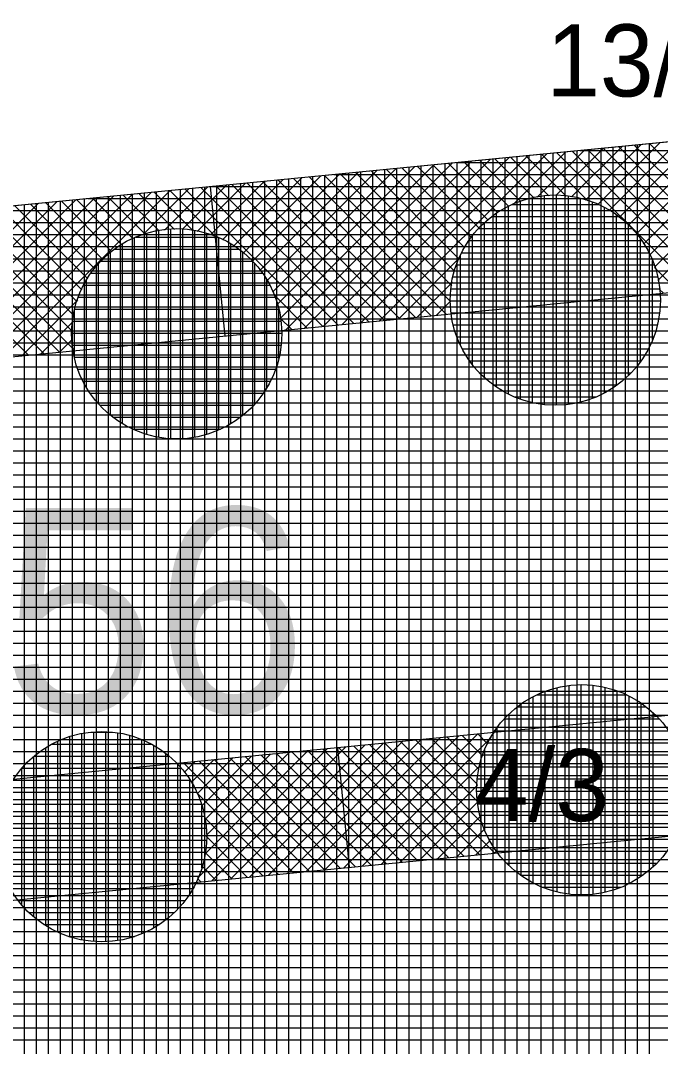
# Model space of a CAD drawing. Extents: x -566461 to -565198, y -1096301 to -1095707.
# Drawn here: x -566328.95 to -566318.3, y -1095853.58 to -1095836.51 of the extents above; entities that cross this region are included whole.
import ezdxf

# ---------------------------------------------------------------- set-up
doc = ezdxf.new("R2010")
doc.units = 0
for name, color, linetype in [('Vrstva 1', 7, 'Continuous'), ('Vrstva 18', 7, 'Continuous'), ('Vrstva 40', 7, 'Continuous'), ('Vrstva 41', 7, 'Continuous'), ('Vrstva 42', 7, 'Continuous'), ('Vrstva 43', 7, 'Continuous'), ('Vrstva 44', 7, 'Continuous')]:
    doc.layers.add(name, color=color, linetype=linetype)

msp = doc.modelspace()

# ---------------------------------------------------------------- linework, layer by layer
at = {"layer": 'Vrstva 1'}
msp.add_line((-566305.22, -1095837.26), (-566355.65, -1095842.19), dxfattribs=at)
at = {"layer": 'Vrstva 41'}
for p, q in [((-566315.801, -1095838.294), (-566318.342, -1095840.835)), ((-566317.369, -1095838.448), (-566318.837, -1095839.916)), ((-566317.055, -1095838.417), (-566318.702, -1095840.064)), ((-566316.742, -1095838.386), (-566318.583, -1095840.228)), ((-566316.428, -1095838.356), (-566318.482, -1095840.409)), ((-566316.115, -1095838.325), (-566318.4, -1095840.61)), ((-566319.25, -1095838.632), (-566320.039, -1095839.421)), ((-566318.936, -1095838.601), (-566319.779, -1095839.443)), ((-566318.623, -1095838.57), (-566319.548, -1095839.495)), ((-566318.309, -1095838.54), (-566319.341, -1095839.571)), ((-566319.251, -1095838.632), (-566316.963, -1095840.92)), ((-566317.996, -1095838.509), (-566319.156, -1095839.669)), ((-566318.994, -1095838.607), (-566316.706, -1095840.894)), ((-566317.682, -1095838.478), (-566318.988, -1095839.784)), ((-566318.736, -1095838.581), (-566316.448, -1095840.869)), ((-566318.478, -1095838.556), (-566316.19, -1095840.844)), ((-566321.131, -1095838.815), (-566323.915, -1095841.599)), ((-566320.817, -1095838.785), (-566323.601, -1095841.569)), ((-566320.504, -1095838.754), (-566323.288, -1095841.538)), ((-566320.19, -1095838.723), (-566322.974, -1095841.507)), ((-566321.055, -1095838.808), (-566320.406, -1095839.457)), ((-566320.797, -1095838.783), (-566320.155, -1095839.425)), ((-566319.877, -1095838.693), (-566320.752, -1095839.568)), ((-566320.54, -1095838.758), (-566319.868, -1095839.429)), ((-566319.563, -1095838.662), (-566320.349, -1095839.448)), ((-566320.282, -1095838.732), (-566319.508, -1095839.507)), ((-566320.024, -1095838.707), (-566317.736, -1095840.995)), ((-566319.767, -1095838.682), (-566317.479, -1095840.97)), ((-566319.509, -1095838.657), (-566317.221, -1095840.945)), ((-566322.698, -1095838.969), (-566324.755, -1095841.025)), ((-566322.385, -1095838.938), (-566324.681, -1095841.234)), ((-566322.071, -1095838.907), (-566324.631, -1095841.467)), ((-566321.758, -1095838.877), (-566324.542, -1095841.66)), ((-566321.444, -1095838.846), (-566324.228, -1095841.63)), ((-566322.859, -1095838.984), (-566321.555, -1095840.288)), ((-566322.601, -1095838.959), (-566321.442, -1095840.118)), ((-566322.343, -1095838.934), (-566321.312, -1095839.965)), ((-566322.086, -1095838.909), (-566321.166, -1095839.828)), ((-566321.828, -1095838.884), (-566321.004, -1095839.707)), ((-566321.57, -1095838.858), (-566320.825, -1095839.604)), ((-566321.313, -1095838.833), (-566320.626, -1095839.52)), ((-566324.579, -1095839.153), (-566325.586, -1095840.159)), ((-566324.266, -1095839.122), (-566325.405, -1095840.261)), ((-566323.952, -1095839.091), (-566325.242, -1095840.381)), ((-566323.639, -1095839.061), (-566325.096, -1095840.517)), ((-566323.325, -1095839.03), (-566324.965, -1095840.669)), ((-566323.012, -1095838.999), (-566324.851, -1095840.838)), ((-566324.662, -1095839.161), (-566322.374, -1095841.449)), ((-566324.404, -1095839.135), (-566322.117, -1095841.423)), ((-566324.147, -1095839.11), (-566321.859, -1095841.398)), ((-566323.889, -1095839.085), (-566321.789, -1095841.186)), ((-566323.632, -1095839.06), (-566321.772, -1095840.92)), ((-566323.374, -1095839.035), (-566321.722, -1095840.686)), ((-566323.116, -1095839.01), (-566321.649, -1095840.476)), ((-566326.147, -1095839.306), (-566326.917, -1095840.076)), ((-566325.833, -1095839.275), (-566326.551, -1095839.993)), ((-566325.52, -1095839.244), (-566326.26, -1095839.985)), ((-566326.208, -1095839.312), (-566323.92, -1095841.6)), ((-566325.206, -1095839.214), (-566326.007, -1095840.015)), ((-566325.95, -1095839.287), (-566323.662, -1095841.575)), ((-566324.893, -1095839.183), (-566325.785, -1095840.075)), ((-566325.693, -1095839.261), (-566323.405, -1095841.549)), ((-566325.435, -1095839.236), (-566323.147, -1095841.524)), ((-566325.177, -1095839.211), (-566322.89, -1095841.499)), ((-566324.92, -1095839.186), (-566322.632, -1095841.474)), ((-566328.028, -1095839.49), (-566330.811, -1095842.273)), ((-566327.714, -1095839.459), (-566330.498, -1095842.243)), ((-566327.401, -1095839.428), (-566330.184, -1095842.212)), ((-566327.087, -1095839.398), (-566329.871, -1095842.181)), ((-566326.774, -1095839.367), (-566329.557, -1095842.151)), ((-566326.46, -1095839.336), (-566329.244, -1095842.12)), ((-566328.012, -1095839.488), (-566327.261, -1095840.239)), ((-566327.754, -1095839.463), (-566327.077, -1095840.14)), ((-566327.496, -1095839.438), (-566326.873, -1095840.061)), ((-566327.239, -1095839.413), (-566326.644, -1095840.007)), ((-566326.981, -1095839.387), (-566326.386, -1095839.982)), ((-566326.723, -1095839.362), (-566326.082, -1095840.003)), ((-566326.466, -1095839.337), (-566325.692, -1095840.111)), ((-566328.655, -1095839.551), (-566331.194, -1095842.091)), ((-566328.341, -1095839.52), (-566331.125, -1095842.304)), ((-566329.815, -1095839.664), (-566328.061, -1095841.418)), ((-566329.558, -1095839.639), (-566328.007, -1095841.19)), ((-566329.3, -1095839.614), (-566327.927, -1095840.987)), ((-566329.042, -1095839.589), (-566327.827, -1095840.804)), ((-566328.785, -1095839.564), (-566327.71, -1095840.638)), ((-566328.527, -1095839.538), (-566327.576, -1095840.489)), ((-566328.269, -1095839.513), (-566327.427, -1095840.356)), ((-566331.104, -1095839.79), (-566328.816, -1095842.078)), ((-566330.846, -1095839.765), (-566328.558, -1095842.053)), ((-566330.588, -1095839.74), (-566328.3, -1095842.028)), ((-566330.331, -1095839.715), (-566328.068, -1095841.977)), ((-566330.073, -1095839.69), (-566328.088, -1095841.675)), ((-566321.642, -1095840.458), (-566322.661, -1095841.477)), ((-566318.397, -1095840.618), (-566317.994, -1095841.02)), ((-566321.762, -1095840.861), (-566322.347, -1095841.446)), ((-566318.319, -1095840.978), (-566318.252, -1095841.046)), ((-566327.994, -1095841.153), (-566328.93, -1095842.089)), ((-566324.741, -1095841.062), (-566324.178, -1095841.625)), ((-566321.789, -1095841.171), (-566322.034, -1095841.415)), ((-566328.077, -1095841.519), (-566328.617, -1095842.059)), ((-566324.633, -1095841.452), (-566324.435, -1095841.65)), ((-566328.085, -1095841.81), (-566328.303, -1095842.028)), ((-566321.341, -1095848.381), (-566323.569, -1095850.609)), ((-566321.339, -1095848.381), (-566321.172, -1095848.548)), ((-566321.082, -1095848.356), (-566321.07, -1095848.368)), ((-566322.909, -1095848.534), (-566325.136, -1095850.762)), ((-566322.595, -1095848.504), (-566324.823, -1095850.732)), ((-566322.282, -1095848.473), (-566324.509, -1095850.701)), ((-566321.968, -1095848.443), (-566324.196, -1095850.67)), ((-566321.655, -1095848.412), (-566323.883, -1095850.64)), ((-566321.117, -1095848.44), (-566323.256, -1095850.578)), ((-566322.885, -1095848.532), (-566321.054, -1095850.363)), ((-566322.628, -1095848.507), (-566321.252, -1095849.883)), ((-566322.37, -1095848.482), (-566321.336, -1095849.515)), ((-566322.112, -1095848.457), (-566321.345, -1095849.224)), ((-566321.855, -1095848.431), (-566321.316, -1095848.971)), ((-566321.597, -1095848.406), (-566321.256, -1095848.748)), ((-566323.849, -1095848.626), (-566326.002, -1095850.779)), ((-566324.163, -1095848.657), (-566325.89, -1095850.384)), ((-566324.79, -1095848.718), (-566325.883, -1095849.812)), ((-566324.476, -1095848.688), (-566325.86, -1095850.072)), ((-566323.536, -1095848.596), (-566325.763, -1095850.824)), ((-566323.222, -1095848.565), (-566325.45, -1095850.793)), ((-566324.689, -1095848.708), (-566322.858, -1095850.54)), ((-566324.431, -1095848.683), (-566322.6, -1095850.514)), ((-566324.174, -1095848.658), (-566322.343, -1095850.489)), ((-566323.916, -1095848.633), (-566322.085, -1095850.464)), ((-566323.658, -1095848.608), (-566321.827, -1095850.439)), ((-566323.401, -1095848.583), (-566321.57, -1095850.414)), ((-566323.143, -1095848.557), (-566321.312, -1095850.388)), ((-566326.357, -1095848.872), (-566326.358, -1095848.873)), ((-566326.235, -1095848.86), (-566324.404, -1095850.691)), ((-566326.043, -1095848.841), (-566326.226, -1095849.023)), ((-566325.73, -1095848.81), (-566326.11, -1095849.191)), ((-566325.417, -1095848.78), (-566326.012, -1095849.375)), ((-566325.977, -1095848.834), (-566324.146, -1095850.666)), ((-566325.103, -1095848.749), (-566325.936, -1095849.582)), ((-566325.72, -1095848.809), (-566323.888, -1095850.64)), ((-566325.462, -1095848.784), (-566323.631, -1095850.615)), ((-566325.204, -1095848.759), (-566323.373, -1095850.59)), ((-566324.947, -1095848.734), (-566323.115, -1095850.565)), ((-566321.301, -1095848.907), (-566322.942, -1095850.548)), ((-566321.346, -1095849.234), (-566322.629, -1095850.517)), ((-566326.023, -1095849.354), (-566324.661, -1095850.716)), ((-566321.337, -1095849.509), (-566322.315, -1095850.487)), ((-566321.292, -1095849.746), (-566322.002, -1095850.456)), ((-566325.89, -1095849.77), (-566324.919, -1095850.741)), ((-566325.859, -1095850.084), (-566325.177, -1095850.766)), ((-566321.222, -1095849.959), (-566321.688, -1095850.425)), ((-566321.132, -1095850.152), (-566321.375, -1095850.395)), ((-566325.885, -1095850.341), (-566325.434, -1095850.791)), ((-566321.023, -1095850.326), (-566321.061, -1095850.364)), ((-566325.931, -1095850.578), (-566325.692, -1095850.817)), ((-566326.005, -1095850.787), (-566325.95, -1095850.842))]:
    msp.add_line(p, q, dxfattribs=at)
at = {"layer": 'Vrstva 42'}
for p, q in [((-566325.792, -1095839.271), (-566325.549, -1095841.759)), ((-566323.674, -1095848.609), (-566323.48, -1095850.6))]:
    msp.add_line(p, q, dxfattribs=at)
for points in [[(-566355.65, -1095842.19), (-566355.093, -1095844.647), (-566304.64, -1095839.715), (-566305.22, -1095837.26)], [(-566353.532, -1095851.528), (-566353.085, -1095853.494), (-566302.553, -1095848.555), (-566303.017, -1095846.59)]]:
    msp.add_lwpolyline(points, close=True, dxfattribs=at)
at = {"layer": 'Vrstva 43'}
for p, q in [((-566319.29, -1095838.635), (-566319.29, -1095859.839)), ((-566319.09, -1095838.616), (-566319.09, -1095859.823)), ((-566318.89, -1095838.596), (-566318.89, -1095859.808)), ((-566318.69, -1095838.577), (-566318.69, -1095859.792)), ((-566318.49, -1095838.557), (-566318.49, -1095859.777)), ((-566321.09, -1095838.811), (-566321.09, -1095859.977)), ((-566320.89, -1095838.792), (-566320.89, -1095859.962)), ((-566320.69, -1095838.772), (-566320.69, -1095859.946)), ((-566320.49, -1095838.753), (-566320.49, -1095859.931)), ((-566320.29, -1095838.733), (-566320.29, -1095859.916)), ((-566320.09, -1095838.714), (-566320.09, -1095859.9)), ((-566319.89, -1095838.694), (-566319.89, -1095859.885)), ((-566319.69, -1095838.675), (-566319.69, -1095859.869)), ((-566319.643, -1095838.67), (-566304.887, -1095838.67)), ((-566319.49, -1095838.655), (-566319.49, -1095859.854)), ((-566322.89, -1095838.987), (-566322.89, -1095860.116)), ((-566322.69, -1095838.968), (-566322.69, -1095860.101)), ((-566322.49, -1095838.948), (-566322.49, -1095860.085)), ((-566322.29, -1095838.929), (-566322.29, -1095860.07)), ((-566322.09, -1095838.909), (-566322.09, -1095860.054)), ((-566321.89, -1095838.89), (-566321.89, -1095860.039)), ((-566321.69, -1095838.87), (-566321.69, -1095860.024)), ((-566321.689, -1095838.87), (-566304.84, -1095838.87)), ((-566321.49, -1095838.851), (-566321.49, -1095860.008)), ((-566321.29, -1095838.831), (-566321.29, -1095859.993)), ((-566324.49, -1095839.144), (-566324.49, -1095860.239)), ((-566324.29, -1095839.124), (-566324.29, -1095860.224)), ((-566324.09, -1095839.105), (-566324.09, -1095860.209)), ((-566323.89, -1095839.085), (-566323.89, -1095860.193)), ((-566323.735, -1095839.07), (-566304.793, -1095839.07)), ((-566323.69, -1095839.066), (-566323.69, -1095860.178)), ((-566323.49, -1095839.046), (-566323.49, -1095860.162)), ((-566323.29, -1095839.027), (-566323.29, -1095860.147)), ((-566323.09, -1095839.007), (-566323.09, -1095860.131)), ((-566326.29, -1095839.32), (-566326.29, -1095860.378)), ((-566326.09, -1095839.3), (-566326.09, -1095860.363)), ((-566325.89, -1095839.281), (-566325.89, -1095860.347)), ((-566325.781, -1095839.27), (-566304.746, -1095839.27)), ((-566325.69, -1095839.261), (-566325.69, -1095860.332)), ((-566325.49, -1095839.242), (-566325.49, -1095860.317)), ((-566325.29, -1095839.222), (-566325.29, -1095860.301)), ((-566325.09, -1095839.202), (-566325.09, -1095860.286)), ((-566324.89, -1095839.183), (-566324.89, -1095860.27)), ((-566324.69, -1095839.163), (-566324.69, -1095860.255)), ((-566328.09, -1095839.496), (-566328.09, -1095860.517)), ((-566327.89, -1095839.476), (-566327.89, -1095860.502)), ((-566327.827, -1095839.47), (-566304.699, -1095839.47)), ((-566327.69, -1095839.457), (-566327.69, -1095860.486)), ((-566327.49, -1095839.437), (-566327.49, -1095860.471)), ((-566327.29, -1095839.418), (-566327.29, -1095860.455)), ((-566327.09, -1095839.398), (-566327.09, -1095860.44)), ((-566326.89, -1095839.378), (-566326.89, -1095860.424)), ((-566326.69, -1095839.359), (-566326.69, -1095860.409)), ((-566326.49, -1095839.339), (-566326.49, -1095860.394)), ((-566329.872, -1095839.67), (-566304.651, -1095839.67)), ((-566328.89, -1095839.574), (-566328.89, -1095860.579)), ((-566328.69, -1095839.554), (-566328.69, -1095860.563)), ((-566328.49, -1095839.535), (-566328.49, -1095860.548)), ((-566328.29, -1095839.515), (-566328.29, -1095860.532)), ((-566331.918, -1095839.87), (-566304.604, -1095839.87)), ((-566333.964, -1095840.07), (-566304.557, -1095840.07)), ((-566336.01, -1095840.27), (-566304.51, -1095840.27)), ((-566338.056, -1095840.47), (-566304.463, -1095840.47)), ((-566340.102, -1095840.67), (-566304.416, -1095840.67)), ((-566342.147, -1095840.87), (-566304.368, -1095840.87)), ((-566344.193, -1095841.07), (-566304.321, -1095841.07)), ((-566346.239, -1095841.27), (-566304.274, -1095841.27)), ((-566348.285, -1095841.47), (-566304.227, -1095841.47)), ((-566350.331, -1095841.67), (-566304.18, -1095841.67)), ((-566352.377, -1095841.87), (-566304.132, -1095841.87)), ((-566354.423, -1095842.07), (-566304.085, -1095842.07)), ((-566355.632, -1095842.27), (-566304.038, -1095842.27)), ((-566355.586, -1095842.47), (-566303.991, -1095842.47)), ((-566355.541, -1095842.67), (-566303.944, -1095842.67)), ((-566355.496, -1095842.87), (-566303.897, -1095842.87)), ((-566355.45, -1095843.07), (-566303.849, -1095843.07)), ((-566355.405, -1095843.27), (-566303.802, -1095843.27)), ((-566355.36, -1095843.47), (-566303.755, -1095843.47)), ((-566355.314, -1095843.67), (-566303.708, -1095843.67)), ((-566355.269, -1095843.87), (-566303.661, -1095843.87)), ((-566355.223, -1095844.07), (-566303.613, -1095844.07)), ((-566355.178, -1095844.27), (-566303.566, -1095844.27)), ((-566355.133, -1095844.47), (-566303.519, -1095844.47)), ((-566355.087, -1095844.67), (-566303.472, -1095844.67)), ((-566355.042, -1095844.87), (-566303.425, -1095844.87)), ((-566354.997, -1095845.07), (-566303.378, -1095845.07)), ((-566354.951, -1095845.27), (-566303.33, -1095845.27)), ((-566354.906, -1095845.47), (-566303.283, -1095845.47)), ((-566354.861, -1095845.67), (-566303.236, -1095845.67)), ((-566354.815, -1095845.87), (-566303.189, -1095845.87)), ((-566354.77, -1095846.07), (-566303.142, -1095846.07)), ((-566354.724, -1095846.27), (-566303.094, -1095846.27)), ((-566354.679, -1095846.47), (-566303.047, -1095846.47)), ((-566354.634, -1095846.67), (-566303, -1095846.67)), ((-566354.588, -1095846.87), (-566302.953, -1095846.87)), ((-566354.543, -1095847.07), (-566302.906, -1095847.07)), ((-566354.498, -1095847.27), (-566302.859, -1095847.27)), ((-566354.452, -1095847.47), (-566302.811, -1095847.47)), ((-566354.407, -1095847.67), (-566302.764, -1095847.67)), ((-566354.361, -1095847.87), (-566302.717, -1095847.87)), ((-566354.316, -1095848.07), (-566302.67, -1095848.07)), ((-566354.271, -1095848.27), (-566302.623, -1095848.27)), ((-566354.225, -1095848.47), (-566302.575, -1095848.47)), ((-566354.18, -1095848.67), (-566302.528, -1095848.67)), ((-566354.135, -1095848.87), (-566302.481, -1095848.87)), ((-566354.089, -1095849.07), (-566302.434, -1095849.07)), ((-566354.044, -1095849.27), (-566302.387, -1095849.27)), ((-566353.998, -1095849.47), (-566302.34, -1095849.47)), ((-566353.953, -1095849.67), (-566302.292, -1095849.67)), ((-566353.908, -1095849.87), (-566302.245, -1095849.87)), ((-566353.862, -1095850.07), (-566302.198, -1095850.07)), ((-566353.817, -1095850.27), (-566302.151, -1095850.27)), ((-566353.772, -1095850.47), (-566302.104, -1095850.47)), ((-566353.726, -1095850.67), (-566302.056, -1095850.67)), ((-566353.681, -1095850.87), (-566302.009, -1095850.87)), ((-566353.635, -1095851.07), (-566301.962, -1095851.07)), ((-566353.59, -1095851.27), (-566301.915, -1095851.27)), ((-566353.545, -1095851.47), (-566301.868, -1095851.47)), ((-566353.499, -1095851.67), (-566301.821, -1095851.67)), ((-566353.454, -1095851.87), (-566301.773, -1095851.87)), ((-566353.409, -1095852.07), (-566301.726, -1095852.07)), ((-566353.363, -1095852.27), (-566301.679, -1095852.27)), ((-566353.318, -1095852.47), (-566301.632, -1095852.47)), ((-566353.272, -1095852.67), (-566301.585, -1095852.67)), ((-566353.227, -1095852.87), (-566301.537, -1095852.87)), ((-566353.182, -1095853.07), (-566301.49, -1095853.07)), ((-566353.136, -1095853.27), (-566301.443, -1095853.27)), ((-566353.091, -1095853.47), (-566301.396, -1095853.47))]:
    msp.add_line(p, q, dxfattribs=at)
msp.add_lwpolyline([(-566355.65, -1095842.19), (-566351.09, -1095862.29), (-566300.24, -1095858.37), (-566305.22, -1095837.26)], close=True, dxfattribs=at)
at = {"layer": 'Vrstva 44'}
for p, q in [((-566320.43, -1095842.868), (-566320.43, -1095839.454)), ((-566320.23, -1095842.899), (-566320.23, -1095839.421)), ((-566320.03, -1095842.908), (-566320.03, -1095839.41)), ((-566319.83, -1095842.894), (-566319.83, -1095839.425)), ((-566319.63, -1095842.858), (-566319.63, -1095839.463)), ((-566320.83, -1095842.725), (-566320.83, -1095839.594)), ((-566320.777, -1095839.57), (-566319.323, -1095839.57)), ((-566320.63, -1095842.809), (-566320.63, -1095839.511)), ((-566319.43, -1095842.796), (-566319.43, -1095839.525)), ((-566319.23, -1095842.704), (-566319.23, -1095839.614)), ((-566321.113, -1095839.77), (-566318.99, -1095839.77)), ((-566321.03, -1095842.608), (-566321.03, -1095839.712)), ((-566319.03, -1095842.58), (-566319.03, -1095839.74)), ((-566326.65, -1095843.442), (-566326.65, -1095839.996)), ((-566326.45, -1095843.465), (-566326.45, -1095839.974)), ((-566326.25, -1095843.466), (-566326.25, -1095839.975)), ((-566326.05, -1095843.443), (-566326.05, -1095839.998)), ((-566321.331, -1095839.97), (-566318.77, -1095839.97)), ((-566321.23, -1095842.45), (-566321.23, -1095839.869)), ((-566318.83, -1095842.412), (-566318.83, -1095839.906)), ((-566327.05, -1095843.322), (-566327.05, -1095840.118)), ((-566327.031, -1095840.11), (-566325.665, -1095840.11)), ((-566326.85, -1095843.397), (-566326.85, -1095840.044)), ((-566325.85, -1095843.395), (-566325.85, -1095840.044)), ((-566325.65, -1095843.322), (-566325.65, -1095840.117)), ((-566321.491, -1095840.17), (-566318.607, -1095840.17)), ((-566321.43, -1095842.233), (-566321.43, -1095840.087)), ((-566318.63, -1095842.181), (-566318.63, -1095840.14)), ((-566327.384, -1095840.31), (-566325.317, -1095840.31)), ((-566327.25, -1095843.219), (-566327.25, -1095840.221)), ((-566325.45, -1095843.22), (-566325.45, -1095840.221)), ((-566327.612, -1095840.51), (-566325.088, -1095840.51)), ((-566327.45, -1095843.08), (-566327.45, -1095840.361)), ((-566325.25, -1095843.079), (-566325.25, -1095840.359)), ((-566321.63, -1095841.909), (-566321.63, -1095840.409)), ((-566321.61, -1095840.37), (-566318.491, -1095840.37)), ((-566318.43, -1095841.817), (-566318.43, -1095840.502)), ((-566327.65, -1095842.889), (-566327.65, -1095840.549)), ((-566325.05, -1095842.891), (-566325.05, -1095840.551)), ((-566321.697, -1095840.57), (-566318.404, -1095840.57)), ((-566327.85, -1095842.619), (-566327.85, -1095840.82)), ((-566327.778, -1095840.71), (-566324.922, -1095840.71)), ((-566324.85, -1095842.62), (-566324.85, -1095840.822)), ((-566321.755, -1095840.77), (-566318.345, -1095840.77)), ((-566327.899, -1095840.91), (-566324.8, -1095840.91)), ((-566321.788, -1095840.97), (-566318.311, -1095840.97)), ((-566327.989, -1095841.11), (-566324.712, -1095841.11)), ((-566321.798, -1095841.17), (-566318.302, -1095841.17)), ((-566328.051, -1095841.31), (-566324.65, -1095841.31)), ((-566328.05, -1095842.133), (-566328.05, -1095841.307)), ((-566324.65, -1095842.129), (-566324.65, -1095841.31)), ((-566321.786, -1095841.37), (-566318.315, -1095841.37)), ((-566328.086, -1095841.51), (-566324.613, -1095841.51)), ((-566328.098, -1095841.71), (-566324.601, -1095841.71)), ((-566321.751, -1095841.57), (-566318.35, -1095841.57)), ((-566321.688, -1095841.77), (-566318.41, -1095841.77)), ((-566328.088, -1095841.91), (-566324.612, -1095841.91)), ((-566321.599, -1095841.97), (-566318.501, -1095841.97)), ((-566328.055, -1095842.11), (-566324.646, -1095842.11)), ((-566321.479, -1095842.17), (-566318.623, -1095842.17)), ((-566327.996, -1095842.31), (-566324.703, -1095842.31)), ((-566321.312, -1095842.37), (-566318.788, -1095842.37)), ((-566327.909, -1095842.51), (-566324.79, -1095842.51)), ((-566321.083, -1095842.57), (-566319.014, -1095842.57)), ((-566327.792, -1095842.71), (-566324.909, -1095842.71)), ((-566327.63, -1095842.91), (-566325.068, -1095842.91)), ((-566320.733, -1095842.77), (-566319.369, -1095842.77)), ((-566327.411, -1095843.11), (-566325.288, -1095843.11)), ((-566327.076, -1095843.31), (-566325.622, -1095843.31)), ((-566320.22, -1095850.949), (-566320.22, -1095847.671)), ((-566320.02, -1095851.011), (-566320.02, -1095847.611)), ((-566319.82, -1095851.047), (-566319.82, -1095847.575)), ((-566319.62, -1095851.059), (-566319.62, -1095847.561)), ((-566319.42, -1095851.048), (-566319.42, -1095847.57)), ((-566319.22, -1095851.014), (-566319.22, -1095847.605)), ((-566319.02, -1095850.957), (-566319.02, -1095847.665)), ((-566320.42, -1095850.861), (-566320.42, -1095847.76)), ((-566320.359, -1095847.73), (-566318.862, -1095847.73)), ((-566318.82, -1095850.87), (-566318.82, -1095847.75)), ((-566318.62, -1095850.751), (-566318.62, -1095847.868)), ((-566320.685, -1095847.93), (-566318.536, -1095847.93)), ((-566320.62, -1095850.737), (-566320.62, -1095847.883)), ((-566318.42, -1095850.592), (-566318.42, -1095848.029)), ((-566320.901, -1095848.13), (-566318.32, -1095848.13)), ((-566320.82, -1095850.574), (-566320.82, -1095848.047)), ((-566327.93, -1095851.807), (-566327.93, -1095848.372)), ((-566327.775, -1095848.35), (-566327.417, -1095848.35)), ((-566327.73, -1095851.833), (-566327.73, -1095848.345)), ((-566327.53, -1095851.837), (-566327.53, -1095848.343)), ((-566327.33, -1095851.818), (-566327.33, -1095848.363)), ((-566321.058, -1095848.33), (-566318.161, -1095848.33)), ((-566321.02, -1095850.344), (-566321.02, -1095848.274)), ((-566328.428, -1095848.55), (-566326.769, -1095848.55)), ((-566328.33, -1095851.678), (-566328.33, -1095848.502)), ((-566328.13, -1095851.756), (-566328.13, -1095848.424)), ((-566327.13, -1095851.775), (-566327.13, -1095848.406)), ((-566326.93, -1095851.705), (-566326.93, -1095848.474)), ((-566321.175, -1095848.53), (-566318.046, -1095848.53)), ((-566328.53, -1095851.571), (-566328.53, -1095848.608)), ((-566326.73, -1095851.607), (-566326.73, -1095848.574)), ((-566326.53, -1095851.473), (-566326.53, -1095848.707)), ((-566321.22, -1095849.992), (-566321.22, -1095848.629)), ((-566328.73, -1095851.424), (-566328.73, -1095848.756)), ((-566328.723, -1095848.75), (-566326.476, -1095848.75)), ((-566326.33, -1095851.292), (-566326.33, -1095848.889)), ((-566321.261, -1095848.73), (-566317.961, -1095848.73)), ((-566328.93, -1095851.227), (-566328.93, -1095848.954)), ((-566328.926, -1095848.95), (-566326.274, -1095848.95)), ((-566321.317, -1095848.93), (-566317.902, -1095848.93)), ((-566329.074, -1095849.15), (-566326.126, -1095849.15)), ((-566326.13, -1095851.037), (-566326.13, -1095849.144)), ((-566321.349, -1095849.13), (-566317.871, -1095849.13)), ((-566329.186, -1095849.35), (-566326.016, -1095849.35)), ((-566321.358, -1095849.33), (-566317.862, -1095849.33)), ((-566329.263, -1095849.55), (-566325.935, -1095849.55)), ((-566325.93, -1095850.607), (-566325.93, -1095849.57)), ((-566321.345, -1095849.53), (-566317.876, -1095849.53)), ((-566321.308, -1095849.73), (-566317.912, -1095849.73)), ((-566329.315, -1095849.75), (-566325.885, -1095849.75)), ((-566329.343, -1095849.95), (-566325.858, -1095849.95)), ((-566321.245, -1095849.93), (-566317.974, -1095849.93)), ((-566329.348, -1095850.15), (-566325.853, -1095850.15)), ((-566321.154, -1095850.13), (-566318.066, -1095850.13)), ((-566329.33, -1095850.35), (-566325.871, -1095850.35)), ((-566321.031, -1095850.33), (-566318.19, -1095850.33)), ((-566329.287, -1095850.55), (-566325.912, -1095850.55)), ((-566320.862, -1095850.53), (-566318.358, -1095850.53)), ((-566329.219, -1095850.75), (-566325.981, -1095850.75)), ((-566320.629, -1095850.73), (-566318.589, -1095850.73)), ((-566320.271, -1095850.93), (-566318.953, -1095850.93)), ((-566329.124, -1095850.95), (-566326.078, -1095850.95)), ((-566328.99, -1095851.15), (-566326.208, -1095851.15)), ((-566328.814, -1095851.35), (-566326.388, -1095851.35)), ((-566328.564, -1095851.55), (-566326.639, -1095851.55)), ((-566328.148, -1095851.75), (-566327.052, -1095851.75))]:
    msp.add_line(p, q, dxfattribs=at)
for centre in [(-566320.05, -1095841.16), (-566326.35, -1095841.72), (-566319.61, -1095849.31), (-566327.6, -1095850.09)]:
    msp.add_circle(centre, 1.75, dxfattribs=at)

# ---------------------------------------------------------------- texts
at = {"layer": 'Vrstva 18'}
msp.add_text('2656', height=3.4, dxfattribs=at).set_placement((-566334.298, -1095848.02))
at = {"layer": 'Vrstva 40'}
for s, p in [('13/40', (-566320.2, -1095837.77)), ('4/3', (-566321.39, -1095849.83))]:
    msp.add_text(s, height=1.2, dxfattribs=at).set_placement(p)

doc.saveas('drawing.dxf')
